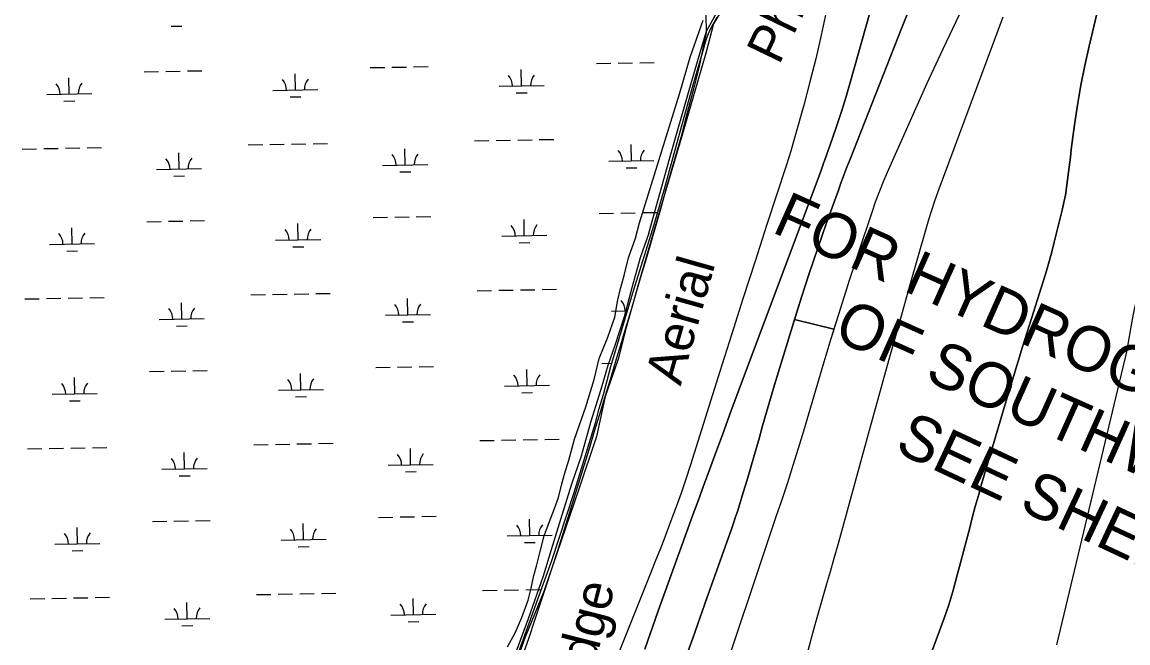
# Model space of a CAD drawing. Extents: x 3925854 to 3964121, y 224593 to 250589.
# Drawn here: x 3941020 to 3943473, y 237197 to 238574 of the extents above; entities that cross this region are included whole.
import ezdxf

# ---------------------------------------------------------------- set-up
doc = ezdxf.new("R2010")
doc.units = 0
for name, color, linetype in [('V-ANNO-TEXT', 7, 'Continuous'), ('V-RIVR-EDGE', 7, 'Continuous'), ('V-RIVR-IDEN', 7, 'Continuous'), ('V-RIVR-JETY', 7, 'Continuous'), ('V-RRAP-FSHR', 7, 'Continuous'), ('V-TOPO-DPTH', 7, 'Continuous'), ('V-TOPO-MAJR', 7, 'Continuous'), ('V-TOPO-MINR', 7, 'Continuous'), ('V-WETL-SWMP', 7, 'Continuous')]:
    doc.layers.add(name, color=color, linetype=linetype)

msp = doc.modelspace()

# ---------------------------------------------------------------- linework, layer by layer
at = {"layer": 'V-RIVR-EDGE'}
msp.add_lwpolyline([(3942587.751, 238627.853), (3942553.969, 238570.525), (3942536.566, 238505.007), (3942485.38, 238325.857), (3942434.195, 238153.874), (3942388.127, 237996.222), (3942359.464, 237893.851), (3942342.06, 237826.286), (3942313.396, 237743.365), (3942293.946, 237654.302), (3942254.021, 237535.551), (3942177.243, 237310.335), (3942136.294, 237208.987), (3942081.014, 237057.478)], dxfattribs=at)
at = {"layer": 'V-RIVR-JETY'}
for points in [[(3942410.702, 238105.889), (3942460.549, 238286.537), (3942498.594, 238417.831), (3942518.118, 238486.293), (3942538.571, 238553.806), (3942560.622, 238594.024)], [(3942389.897, 238128.442), (3942479.429, 238417.226), (3942501.881, 238496.007), (3942530.957, 238578.48)], [(3942096.81, 237188.076), (3942114.027, 237219.116), (3942128.55, 237253.315), (3942142.345, 237291.435), (3942148.95, 237317.924), (3942155.579, 237346.366), (3942162.143, 237369.73), (3942170.001, 237402.457), (3942178.236, 237434.004), (3942189.994, 237465.896), (3942201.323, 237495.059), (3942210.246, 237519.563), (3942216.47, 237546.839), (3942223.435, 237570.979), (3942233.223, 237601.723), (3942245.568, 237648.461), (3942270.363, 237720.435), (3942288.756, 237781.161), (3942300.313, 237827.517), (3942319.708, 237875.332), (3942334.756, 237919.687), (3942341.075, 237953.998), (3942346.887, 237979.714), (3942355.908, 238011.645), (3942365.028, 238050.997), (3942380.458, 238094.566), (3942389.897, 238128.442)], [(3942410.702, 238105.889), (3942391.216, 238051.042), (3942372.745, 237984.453), (3942355.478, 237920.195), (3942335.09, 237856.367), (3942319.655, 237812.409), (3942303.707, 237759.075), (3942281.234, 237685.507), (3942259.925, 237611.14), (3942239.166, 237548.883), (3942214.674, 237470.26), (3942193.854, 237403.313), (3942175.879, 237344.533), (3942142.972, 237250.389), (3942112.176, 237167.94)]]:
    msp.add_lwpolyline(points, dxfattribs=at)
at = {"layer": 'V-RRAP-FSHR'}
for points in [[(3942537.128, 238590.768), (3942537.322, 238551.174), (3942529.722, 238511.905), (3942521.391, 238472.86), (3942511.403, 238434.409), (3942501.556, 238395.272), (3942491.349, 238356.597), (3942481.479, 238317.946), (3942470.262, 238279.429), (3942459.359, 238240.943), (3942448.451, 238202.459), (3942437.548, 238163.975), (3942426.486, 238125.534), (3942415.317, 238087.124), (3942404.149, 238048.715), (3942392.981, 238010.305), (3942381.693, 237971.932), (3942370.214, 237933.614), (3942358.734, 237895.298), (3942347.255, 237856.98), (3942335.776, 237818.662), (3942324.295, 237780.346), (3942312.816, 237742.269), (3942301.137, 237703.771), (3942289.414, 237665.526), (3942277.691, 237627.284), (3942265.968, 237589.4), (3942254.246, 237550.795), (3942242.523, 237512.553)], [(3942242.523, 237512.553), (3942230.718, 237474.333), (3942218.696, 237436.183), (3942206.673, 237398.34), (3942194.294, 237359.998), (3942181.822, 237321.993), (3942169.35, 237283.986), (3942156.853, 237245.99), (3942143.983, 237208.116), (3942131.116, 237170.242)]]:
    msp.add_lwpolyline(points, dxfattribs=at)
at = {"layer": 'V-TOPO-DPTH'}
for points in [[(3942401.408, 237182.834), (3942430.279, 237265.367), (3942459.778, 237347.683), (3942496.935, 237449.538), (3942508.336, 237480.762), (3942519.749, 237511.982), (3942531.18, 237543.195), (3942542.624, 237574.403), (3942556.118, 237611.167), (3942574.363, 237660.738), (3942592.668, 237710.286), (3942611.063, 237759.801), (3942629.518, 237809.293), (3942792.479, 238245.099), (3942794.416, 238250.317), (3942796.337, 238255.54), (3942798.234, 238260.772), (3942800.115, 238266.01), (3942818.106, 238316.488), (3942828.657, 238347.069), (3942838.79, 238377.783), (3942848.296, 238408.697), (3942857.385, 238439.744), (3942996.497, 238933.506)], [(3943433.263, 238714.738), (3943387.141, 238520.986), (3943377.513, 238477.541), (3943368.794, 238433.928), (3943361.438, 238390.066), (3943354.992, 238346.036), (3943347.871, 238291.477), (3943345.713, 238274.596), (3943343.613, 238257.707), (3943341.601, 238240.807), (3943339.648, 238223.901), (3943337.413, 238207.048), (3943334.743, 238190.272), (3943331.423, 238173.613), (3943327.669, 238157.032), (3943310.101, 238085.898), (3943304.599, 238064.511), (3943298.824, 238043.2), (3943292.638, 238022.005), (3943286.178, 238000.887), (3943259.521, 237916.656), (3943239.73, 237853.418), (3943220.211, 237790.097), (3943201.099, 237726.652), (3943182.259, 237663.125), (3943148.7, 237548.622), (3943141.606, 237523.874), (3943134.708, 237499.073), (3943128.104, 237474.192), (3943121.696, 237449.258), (3943115.356, 237424.304), (3943108.912, 237399.378), (3943102.31, 237374.493), (3943095.604, 237349.635), (3943085.005, 237310.833), (3943080.696, 237295.834), (3943076.129, 237280.917), (3943071.172, 237266.125), (3943065.958, 237251.416), (3942854.264, 236678.222)], [(3942854.264, 236678.222), (3943065.958, 237251.416), (3943071.172, 237266.125), (3943076.129, 237280.917), (3943080.696, 237295.834), (3943085.005, 237310.833), (3943095.604, 237349.635), (3943102.31, 237374.493), (3943108.912, 237399.378), (3943115.356, 237424.304), (3943121.696, 237449.258), (3943128.104, 237474.192), (3943134.708, 237499.073), (3943141.606, 237523.874), (3943148.7, 237548.622), (3943182.259, 237663.125), (3943201.099, 237726.652), (3943220.211, 237790.097), (3943239.73, 237853.418), (3943259.521, 237916.656), (3943286.178, 238000.887), (3943292.638, 238022.005), (3943298.824, 238043.2), (3943304.599, 238064.511), (3943310.101, 238085.898), (3943327.669, 238157.032), (3943331.423, 238173.613), (3943334.743, 238190.272), (3943337.413, 238207.048), (3943339.648, 238223.901), (3943341.601, 238240.807), (3943343.613, 238257.707), (3943345.713, 238274.596), (3943347.871, 238291.477), (3943354.992, 238346.036), (3943361.438, 238390.066), (3943368.794, 238433.928), (3943377.513, 238477.541), (3943387.141, 238520.986), (3943433.263, 238714.738)], [(3942997.163, 238625.236), (3942971.398, 238560.117), (3942856.831, 238269.643), (3942849.984, 238252.051), (3942843.242, 238234.418), (3942836.66, 238216.725), (3942830.184, 238198.993), (3942804.15, 238126.702), (3942785.147, 238072.657), (3942766.69, 238018.431), (3942749.054, 237963.933), (3942731.966, 237909.253), (3942689.407, 237769.378), (3942680.301, 237739.005), (3942671.359, 237708.585), (3942662.666, 237678.092), (3942654.137, 237647.552), (3942652.908, 237643.08), (3942644.982, 237614.779), (3942636.874, 237586.532), (3942628.493, 237558.364), (3942619.93, 237530.25), (3942609.81, 237497.59), (3942606.101, 237485.868), (3942602.3, 237474.178), (3942598.359, 237462.533), (3942594.325, 237450.92), (3942539.462, 237295.96), (3942507.685, 237206.978), (3942475.586, 237118.114)], [(3942821.152, 237892.549), (3942733.423, 237913.917), (3942749.054, 237963.933), (3942766.69, 238018.431), (3942785.147, 238072.657), (3942804.15, 238126.702), (3942830.184, 238198.993), (3942836.66, 238216.725), (3942843.242, 238234.418), (3942849.984, 238252.051), (3942856.831, 238269.643), (3942971.398, 238560.117), (3942997.163, 238625.236)], [(3943099.14, 238590.556), (3943062.41, 238513.884), (3943026.829, 238436.645), (3942942.176, 238247.271), (3942931.851, 238223.209), (3942922.014, 238198.957), (3942912.91, 238174.421), (3942904.294, 238149.695), (3942877.33, 238068.399), (3942855.91, 238002.785), (3942834.905, 237937.04), (3942814.522, 237871.1), (3942794.554, 237805.029), (3942753.313, 237666.201), (3942741.765, 237628.07), (3942729.947, 237590.023), (3942717.727, 237552.104), (3942705.238, 237514.269), (3942692.551, 237476.498), (3942679.869, 237438.724), (3942667.195, 237400.948), (3942654.526, 237363.171), (3942592.369, 237177.768)], [(3943099.14, 238590.556), (3943062.41, 238513.884), (3943026.829, 238436.645), (3942942.176, 238247.271), (3942931.851, 238223.209), (3942922.014, 238198.957), (3942912.91, 238174.421), (3942904.294, 238149.695), (3942877.33, 238068.399), (3942855.91, 238002.785), (3942834.905, 237937.04), (3942821.152, 237892.549)], [(3942759.807, 237163.66), (3942779.706, 237237.593), (3942804.876, 237325.117), (3942813.417, 237355.013), (3942821.887, 237384.928), (3942830.253, 237414.873), (3942838.548, 237444.837), (3942897.852, 237660.533), (3942920.749, 237743.398), (3942943.786, 237826.224), (3942967.035, 237908.99), (3942990.423, 237991.718), (3943025.489, 238115.146), (3943031.697, 238136.049), (3943038.232, 238156.845), (3943045.26, 238177.48), (3943052.616, 238198.007), (3943196.816, 238585.863)], [(3942759.807, 237163.66), (3942779.706, 237237.593), (3942804.876, 237325.117), (3942813.417, 237355.013), (3942821.887, 237384.928), (3942830.253, 237414.873), (3942838.548, 237444.837), (3942897.852, 237660.533), (3942920.749, 237743.398), (3942943.786, 237826.224), (3942967.035, 237908.99), (3942990.423, 237991.718), (3943025.489, 238115.146), (3943031.697, 238136.049), (3943038.232, 238156.845), (3943045.26, 238177.48), (3943052.616, 238198.007), (3943196.816, 238585.863)], [(3942475.586, 237118.114), (3942507.685, 237206.978), (3942539.462, 237295.96), (3942594.325, 237450.92), (3942598.359, 237462.533), (3942602.3, 237474.178), (3942606.101, 237485.868), (3942609.81, 237497.59), (3942619.93, 237530.25), (3942628.493, 237558.364), (3942636.874, 237586.532), (3942644.982, 237614.779), (3942652.908, 237643.08), (3942654.137, 237647.552), (3942662.666, 237678.092), (3942671.359, 237708.585), (3942680.301, 237739.005), (3942689.407, 237769.378), (3942731.966, 237909.253), (3942733.423, 237913.917), (3942821.152, 237892.549), (3942819.979, 237888.753)], [(3942819.979, 237888.753), (3942814.522, 237871.1), (3942794.554, 237805.029), (3942753.313, 237666.201), (3942741.765, 237628.07), (3942729.947, 237590.023), (3942717.727, 237552.104), (3942705.238, 237514.269), (3942692.551, 237476.498), (3942679.869, 237438.724), (3942667.195, 237400.948), (3942654.526, 237363.171), (3942592.369, 237177.768)]]:
    msp.add_lwpolyline(points, dxfattribs=at)
at = {"layer": 'V-TOPO-MAJR'}
msp.add_lwpolyline([(3943709.827, 238602.641), (3943599.081, 238288.01), (3943580.023, 238233.044), (3943561.31, 238177.962), (3943543.114, 238122.708), (3943525.263, 238067.338), (3943504.199, 238000.938), (3943497.601, 237978.569), (3943491.615, 237956.051), (3943486.55, 237933.308), (3943482.097, 237910.415), (3943470.37, 237842.821), (3943315.156, 237192.34)], dxfattribs=at)
at = {"layer": 'V-TOPO-MINR'}
for points in [[(3942996.497, 238933.506), (3942857.385, 238439.744), (3942848.296, 238408.697), (3942838.79, 238377.783), (3942828.657, 238347.069), (3942818.106, 238316.488), (3942800.115, 238266.01), (3942798.234, 238260.772), (3942796.337, 238255.54), (3942794.416, 238250.317), (3942792.479, 238245.099), (3942629.518, 237809.293), (3942611.063, 237759.801), (3942592.668, 237710.286), (3942574.363, 237660.738), (3942556.118, 237611.167), (3942542.624, 237574.403), (3942531.18, 237543.195), (3942519.749, 237511.982), (3942508.336, 237480.762), (3942496.935, 237449.538), (3942459.778, 237347.683), (3942430.279, 237265.367), (3942401.408, 237182.834)], [(3943433.263, 238714.738), (3943387.141, 238520.986), (3943377.513, 238477.541), (3943368.794, 238433.928), (3943361.438, 238390.066), (3943354.992, 238346.036), (3943347.871, 238291.477), (3943345.713, 238274.596), (3943343.613, 238257.707), (3943341.601, 238240.807), (3943339.648, 238223.901), (3943337.413, 238207.048), (3943334.743, 238190.272), (3943331.423, 238173.613), (3943327.669, 238157.032), (3943310.101, 238085.898), (3943304.599, 238064.511), (3943298.824, 238043.2), (3943292.638, 238022.005), (3943286.178, 238000.887), (3943259.521, 237916.656), (3943239.73, 237853.418), (3943220.211, 237790.097), (3943201.099, 237726.652), (3943182.259, 237663.125), (3943148.7, 237548.622), (3943141.606, 237523.874), (3943134.708, 237499.073), (3943128.104, 237474.192), (3943121.696, 237449.258), (3943115.356, 237424.304), (3943108.912, 237399.378), (3943102.31, 237374.493), (3943095.604, 237349.635), (3943085.005, 237310.833), (3943080.696, 237295.834), (3943076.129, 237280.917), (3943071.172, 237266.125), (3943065.958, 237251.416), (3942854.264, 236678.222)], [(3942997.163, 238625.236), (3942971.398, 238560.117), (3942856.831, 238269.643), (3942849.984, 238252.051), (3942843.242, 238234.418), (3942836.66, 238216.725), (3942830.184, 238198.993), (3942804.15, 238126.702), (3942785.147, 238072.657), (3942766.69, 238018.431), (3942749.054, 237963.933), (3942731.966, 237909.253), (3942689.407, 237769.378), (3942680.301, 237739.005), (3942671.359, 237708.585), (3942662.666, 237678.092), (3942654.137, 237647.552), (3942652.908, 237643.08), (3942644.982, 237614.779), (3942636.874, 237586.532), (3942628.493, 237558.364), (3942619.93, 237530.25), (3942609.81, 237497.59), (3942606.101, 237485.868), (3942602.3, 237474.178), (3942598.359, 237462.533), (3942594.325, 237450.92), (3942539.462, 237295.96), (3942507.685, 237206.978), (3942475.586, 237118.114)], [(3942803.99, 238596.722), (3942792.709, 238544.741), (3942780.745, 238492.925), (3942767.754, 238441.357), (3942754.08, 238389.953), (3942734.666, 238319.784), (3942730.073, 238303.623), (3942725.333, 238287.507), (3942720.369, 238271.458), (3942715.257, 238255.455), (3942672.5, 238124.736), (3942646.031, 238043.363), (3942619.741, 237961.933), (3942593.717, 237880.418), (3942567.872, 237798.845), (3942502.531, 237591.435), (3942492.408, 237560.249), (3942481.927, 237529.186), (3942470.909, 237498.31), (3942459.533, 237467.559), (3942447.805, 237436.933), (3942435.964, 237406.351), (3942423.956, 237375.834), (3942411.836, 237345.361), (3942268.166, 236986.995)], [(3943099.14, 238590.556), (3943062.41, 238513.884), (3943026.829, 238436.645), (3942942.176, 238247.271), (3942931.851, 238223.209), (3942922.014, 238198.957), (3942912.91, 238174.421), (3942904.294, 238149.695), (3942877.33, 238068.399), (3942855.91, 238002.785), (3942834.905, 237937.04), (3942814.522, 237871.1), (3942794.554, 237805.029), (3942753.313, 237666.201), (3942741.765, 237628.07), (3942729.947, 237590.023), (3942717.727, 237552.104), (3942705.238, 237514.269), (3942692.551, 237476.498), (3942679.869, 237438.724), (3942667.195, 237400.948), (3942654.526, 237363.171), (3942592.369, 237177.768)], [(3942759.807, 237163.66), (3942779.706, 237237.593), (3942804.876, 237325.117), (3942813.417, 237355.013), (3942821.887, 237384.928), (3942830.253, 237414.873), (3942838.548, 237444.837), (3942897.852, 237660.533), (3942920.749, 237743.398), (3942943.786, 237826.224), (3942967.035, 237908.99), (3942990.423, 237991.718), (3943025.489, 238115.146), (3943031.697, 238136.049), (3943038.232, 238156.845), (3943045.26, 238177.48), (3943052.616, 238198.007), (3943196.816, 238585.863)]]:
    msp.add_lwpolyline(points, dxfattribs=at)
at = {"layer": 'V-WETL-SWMP'}
for p, q in [((3941350.189, 238564.977), (3941374.186, 238565.413)), ((3942543.413, 238551.155), (3942552.884, 238569.616)), ((3942552.884, 238569.616), (3942561.719, 238585.057)), ((3942537.392, 238534.676), (3942543.413, 238551.155)), ((3942530.689, 238510.74), (3942537.392, 238534.676)), ((3942505.788, 238424.457), (3942530.689, 238510.74)), ((3941386.594, 238465.621), (3941418.589, 238466.203)), ((3941792.435, 238473.001), (3941824.429, 238473.583)), ((3941840.427, 238473.874), (3941872.421, 238474.455)), ((3941888.419, 238474.746), (3941920.414, 238475.328)), ((3942128.067, 238432.666), (3942127.413, 238468.66)), ((3942294.26, 238482.126), (3942326.254, 238482.707)), ((3942342.252, 238482.998), (3942374.247, 238483.58)), ((3942390.244, 238483.871), (3942422.239, 238484.453)), ((3941124.417, 238414.417), (3941123.763, 238450.411)), ((3941290.61, 238463.876), (3941322.604, 238464.458)), ((3941338.602, 238464.749), (3941370.596, 238465.331)), ((3941626.242, 238423.541), (3941625.588, 238459.535)), ((3941576.251, 238422.632), (3941676.234, 238424.45)), ((3942078.076, 238431.757), (3942178.059, 238433.575)), ((3942116.35, 238417.019), (3942140.346, 238417.456)), ((3942473.501, 238306.781), (3942505.788, 238424.457)), ((3941074.426, 238413.508), (3941174.409, 238415.326)), ((3941112.7, 238398.77), (3941136.696, 238399.206)), ((3941614.525, 238407.895), (3941638.521, 238408.331)), ((3941115.758, 238294.168), (3941147.753, 238294.75)), ((3941163.75, 238295.041), (3941195.745, 238295.623)), ((3941521.599, 238301.548), (3941553.594, 238302.13)), ((3941569.591, 238302.42), (3941601.586, 238303.002)), ((3941617.583, 238303.293), (3941649.578, 238303.875)), ((3941665.575, 238304.166), (3941697.57, 238304.747)), ((3942023.424, 238310.672), (3942055.419, 238311.254)), ((3942071.416, 238311.545), (3942103.411, 238312.127)), ((3942119.408, 238312.418), (3942151.403, 238313)), ((3942167.4, 238313.29), (3942199.395, 238313.872)), ((3942371.605, 238266.253), (3942370.951, 238302.247)), ((3942445, 238203.993), (3942473.501, 238306.781)), ((3941019.774, 238292.423), (3941051.769, 238293.005)), ((3941067.766, 238293.296), (3941099.761, 238293.877)), ((3941367.955, 238248.004), (3941367.301, 238283.998)), ((3941869.78, 238257.128), (3941869.126, 238293.122)), ((3941317.963, 238247.095), (3941417.947, 238248.913)), ((3941819.788, 238256.219), (3941919.772, 238258.037)), ((3942321.613, 238265.344), (3942421.597, 238267.162)), ((3942359.888, 238250.606), (3942383.884, 238251.043)), ((3941356.238, 238232.357), (3941380.234, 238232.793)), ((3941858.063, 238241.482), (3941882.059, 238241.918)), ((3942422.395, 238125.15), (3942445, 238203.993)), ((3942300.308, 238149.506), (3942332.303, 238150.087)), ((3942348.3, 238150.378), (3942380.295, 238150.96)), ((3942396.292, 238151.251), (3942428.287, 238151.833)), ((3941296.658, 238131.256), (3941328.652, 238131.838)), ((3941344.65, 238132.129), (3941376.645, 238132.711)), ((3941392.642, 238133.001), (3941424.637, 238133.583)), ((3941632.29, 238090.921), (3941631.636, 238126.915)), ((3941798.483, 238140.381), (3941830.477, 238140.963)), ((3941846.475, 238141.254), (3941878.47, 238141.835)), ((3941894.467, 238142.126), (3941926.462, 238142.708)), ((3942134.116, 238100.046), (3942133.461, 238136.04)), ((3942372.74, 237966.036), (3942422.395, 238125.15)), ((3941130.465, 238081.797), (3941129.811, 238117.791)), ((3942084.124, 238099.137), (3942184.107, 238100.955)), ((3941080.474, 238080.888), (3941180.457, 238082.706)), ((3941582.299, 238090.012), (3941682.282, 238091.83)), ((3941620.573, 238075.275), (3941644.569, 238075.711)), ((3942122.398, 238084.399), (3942146.394, 238084.836)), ((3941118.748, 238066.15), (3941142.744, 238066.586)), ((3942029.472, 237978.052), (3942061.467, 237978.634)), ((3942077.464, 237978.925), (3942109.459, 237979.507)), ((3942125.456, 237979.798), (3942157.451, 237980.38)), ((3942173.448, 237980.67), (3942205.443, 237981.252)), ((3941025.822, 237959.803), (3941057.817, 237960.385)), ((3941073.814, 237960.676), (3941105.809, 237961.257)), ((3941121.806, 237961.548), (3941153.801, 237962.13)), ((3941169.798, 237962.421), (3941201.793, 237963.003)), ((3941374.003, 237915.384), (3941373.349, 237951.378)), ((3941527.647, 237968.928), (3941559.642, 237969.509)), ((3941575.639, 237969.8), (3941607.634, 237970.382)), ((3941623.631, 237970.673), (3941655.626, 237971.255)), ((3941671.623, 237971.546), (3941703.618, 237972.127)), ((3941875.828, 237924.508), (3941875.174, 237960.502)), ((3942325.888, 237809.797), (3942372.74, 237966.036)), ((3942327.661, 237932.724), (3942362.943, 237933.366)), ((3941324.011, 237914.475), (3941423.995, 237916.293)), ((3941825.836, 237923.599), (3941925.82, 237925.417)), ((3941864.111, 237908.862), (3941888.107, 237909.298)), ((3941362.286, 237899.737), (3941386.282, 237900.173)), ((3941804.531, 237807.761), (3941836.526, 237808.343)), ((3941852.523, 237808.634), (3941884.518, 237809.215)), ((3941900.515, 237809.506), (3941932.51, 237810.088)), ((3942140.164, 237767.426), (3942139.509, 237803.42)), ((3942306.356, 237816.886), (3942328.132, 237817.282)), ((3942310.136, 237747.535), (3942325.888, 237809.797)), ((3941136.513, 237749.177), (3941135.859, 237785.171)), ((3941302.706, 237798.636), (3941334.7, 237799.218)), ((3941350.698, 237799.509), (3941382.693, 237800.091)), ((3941398.69, 237800.381), (3941430.685, 237800.963)), ((3941638.339, 237758.301), (3941637.684, 237794.295)), ((3941588.347, 237757.392), (3941688.33, 237759.21)), ((3942090.172, 237766.517), (3942190.155, 237768.335)), ((3941086.522, 237748.268), (3941186.505, 237750.086)), ((3941124.796, 237733.53), (3941148.792, 237733.966)), ((3941626.621, 237742.655), (3941650.617, 237743.091)), ((3942128.446, 237751.779), (3942152.442, 237752.216)), ((3942300.325, 237716.429), (3942310.136, 237747.535)), ((3942292.165, 237684.749), (3942300.325, 237716.429)), ((3942244.205, 237528.378), (3942292.165, 237684.749)), ((3941533.695, 237636.308), (3941565.69, 237636.889)), ((3941581.687, 237637.18), (3941613.682, 237637.762)), ((3941629.679, 237638.053), (3941661.674, 237638.635)), ((3941677.671, 237638.926), (3941709.666, 237639.507)), ((3942035.52, 237645.432), (3942067.515, 237646.014)), ((3942083.512, 237646.305), (3942115.507, 237646.887)), ((3942131.504, 237647.178), (3942163.499, 237647.759)), ((3942179.496, 237648.05), (3942211.491, 237648.632)), ((3941031.87, 237627.183), (3941063.865, 237627.765)), ((3941079.862, 237628.056), (3941111.857, 237628.637)), ((3941127.854, 237628.928), (3941159.849, 237629.51)), ((3941175.846, 237629.801), (3941207.841, 237630.383)), ((3941380.051, 237582.764), (3941379.397, 237618.758)), ((3941881.876, 237591.888), (3941881.222, 237627.882)), ((3941330.059, 237581.855), (3941430.043, 237583.673)), ((3941831.884, 237590.979), (3941931.868, 237592.797)), ((3941368.334, 237567.117), (3941392.33, 237567.553)), ((3941870.159, 237576.242), (3941894.155, 237576.678)), ((3942194.959, 237379.21), (3942244.205, 237528.378)), ((3941308.754, 237466.016), (3941340.749, 237466.598)), ((3941356.746, 237466.889), (3941388.741, 237467.471)), ((3941404.738, 237467.761), (3941436.733, 237468.343)), ((3941644.387, 237425.681), (3941643.732, 237461.675)), ((3941810.579, 237475.141), (3941842.574, 237475.723)), ((3941858.571, 237476.013), (3941890.566, 237476.595)), ((3941906.563, 237476.886), (3941938.558, 237477.468)), ((3942146.212, 237434.806), (3942145.557, 237470.8)), ((3941142.562, 237416.557), (3941141.907, 237452.551)), ((3942096.22, 237433.897), (3942196.203, 237435.715)), ((3941092.57, 237415.648), (3941192.553, 237417.466)), ((3941594.395, 237424.772), (3941694.378, 237426.59)), ((3942134.494, 237419.159), (3942158.49, 237419.596)), ((3941130.844, 237400.91), (3941154.84, 237401.346)), ((3941632.669, 237410.035), (3941656.665, 237410.471)), ((3942113.752, 237154.45), (3942194.959, 237379.21)), ((3942041.568, 237312.812), (3942073.563, 237313.394)), ((3942089.56, 237313.685), (3942121.555, 237314.267)), ((3942137.552, 237314.558), (3942169.547, 237315.139)), ((3941037.918, 237294.563), (3941069.913, 237295.145)), ((3941085.91, 237295.436), (3941117.905, 237296.017)), ((3941133.902, 237296.308), (3941165.897, 237296.89)), ((3941181.894, 237297.181), (3941213.889, 237297.763)), ((3941539.743, 237303.688), (3941571.738, 237304.269)), ((3941587.735, 237304.56), (3941619.73, 237305.142)), ((3941635.727, 237305.433), (3941667.722, 237306.015)), ((3941683.719, 237306.306), (3941715.714, 237306.887)), ((3941887.924, 237259.268), (3941887.27, 237295.262)), ((3941386.099, 237250.144), (3941385.445, 237286.138)), ((3941336.107, 237249.235), (3941436.091, 237251.053)), ((3941837.933, 237258.359), (3941937.916, 237260.177)), ((3941876.207, 237243.622), (3941900.203, 237244.058)), ((3941374.382, 237234.497), (3941398.378, 237234.933))]:
    msp.add_line(p, q, dxfattribs=at)
for centre, start, end in [((3941571, 238423.012), 0.269879, 41.813537), ((3941681.468, 238425.02), 140.269876, 181.813534), ((3942072.825, 238432.136), 0.269879, 41.813537), ((3942183.293, 238434.145), 140.269876, 181.813534), ((3941069.175, 238413.887), 0.269879, 41.813537), ((3941179.643, 238415.896), 140.269876, 181.813534), ((3941312.713, 238247.474), 0.269879, 41.813537), ((3941423.18, 238249.483), 140.269876, 181.813534), ((3941814.538, 238256.599), 0.269879, 41.813537), ((3941925.005, 238258.607), 140.269876, 181.813534), ((3942316.363, 238265.723), 0.269879, 41.813537), ((3942426.83, 238267.732), 140.269876, 181.813534), ((3942078.873, 238099.516), 0.269879, 41.813537), ((3942189.341, 238101.525), 140.269876, 181.813534), ((3941075.223, 238081.267), 0.269879, 41.813537), ((3941185.691, 238083.276), 140.269876, 181.813534), ((3941577.048, 238090.392), 0.269879, 41.813537), ((3941687.516, 238092.4), 140.269876, 181.813534), ((3942322.411, 237933.103), 0.269879, 41.813537), ((3941318.761, 237914.854), 0.269879, 41.813537), ((3941429.228, 237916.863), 140.269876, 181.813534), ((3941820.586, 237923.979), 0.269879, 41.813537), ((3941931.053, 237925.987), 140.269876, 181.813534), ((3941583.096, 237757.772), 0.269879, 41.813537), ((3941693.564, 237759.78), 140.269876, 181.813534), ((3942084.921, 237766.896), 0.269879, 41.813537), ((3942195.389, 237768.905), 140.269876, 181.813534), ((3941081.271, 237748.647), 0.269879, 41.813537), ((3941191.739, 237750.656), 140.269876, 181.813534), ((3941826.634, 237591.359), 0.269879, 41.813537), ((3941937.101, 237593.367), 140.269876, 181.813534), ((3941324.809, 237582.234), 0.269879, 41.813537), ((3941435.276, 237584.243), 140.269876, 181.813534), ((3941087.319, 237416.027), 0.269879, 41.813537), ((3941197.787, 237418.036), 140.269876, 181.813534), ((3941589.144, 237425.152), 0.269879, 41.813537), ((3941699.612, 237427.16), 140.269876, 181.813534), ((3942090.969, 237434.276), 0.269879, 41.813537), ((3942201.437, 237436.285), 140.269876, 181.813534), ((3941330.857, 237249.614), 0.269879, 41.813537), ((3941441.324, 237251.623), 140.269876, 181.813534), ((3941832.682, 237258.739), 0.269879, 41.813537), ((3941943.149, 237260.747), 140.269876, 181.813534)]:
    msp.add_arc(centre, 35.246, start, end, dxfattribs=at)

# ---------------------------------------------------------------- texts
at = {"layer": 'V-ANNO-TEXT'}
for s, rotation, p in [('FOR HYDROGRAPHIC SURVEY', 335.98098, (3942680.798, 238108.929)), ('OF SOUTHWEST PASS', 335.902921, (3942816.486, 237871.977)), ('SEE SHEET 73', 334.928642, (3942952.953, 237622.557))]:
    msp.add_text(s, height=99.9998, rotation=rotation, dxfattribs=at).set_placement(p)
at = {"layer": 'V-RIVR-IDEN'}
for s, rotation, p in [('Photos', 64.263319, (3942699.341, 238477.025)), ('Aerial', 74.164552, (3942480.856, 237765.324)), ('Edge', 75.647103, (3942271.428, 237071.942))]:
    msp.add_text(s, height=82.9998, rotation=rotation, dxfattribs=at).set_placement(p)

doc.saveas('drawing.dxf')
